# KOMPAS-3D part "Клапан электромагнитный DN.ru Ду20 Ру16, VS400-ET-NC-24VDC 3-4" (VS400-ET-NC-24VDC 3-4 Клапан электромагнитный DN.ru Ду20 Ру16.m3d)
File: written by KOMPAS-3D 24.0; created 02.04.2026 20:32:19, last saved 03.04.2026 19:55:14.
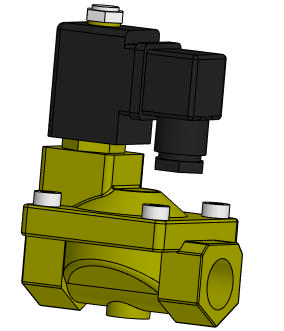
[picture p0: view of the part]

Document properties: Автор: artio; Полное имя файла: C:\Users\artio\OneDrive\Рабочий стол\Клапан электромагнитный DN.ru\VS400-ET-NC\VS400-ET-NC-24VDC 3-4 Клапан электромагнитный DN.ru Ду20 Ру16.m3d

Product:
- Body: Тело 1  | qty 1
    Масса: 1.210539
- Part/product: Клапан электромагнитный DN.ru Ду20 Ру16  | designation VS400-ET-NC-24VDC 3-4
    Масса: 0.954
    Раздел спецификации: Прочие изделия
    Примечание: D130-04719
    additional columns: ef56311e-7521-43dc-8291-0e6108b3d81d; VS400-ET-NC-220VAC 3-4; artio; c; Шероховатость не задана; Да

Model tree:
1. Операция без истории:1

Expressions: VS400-ET-NC-24VDC 3-4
